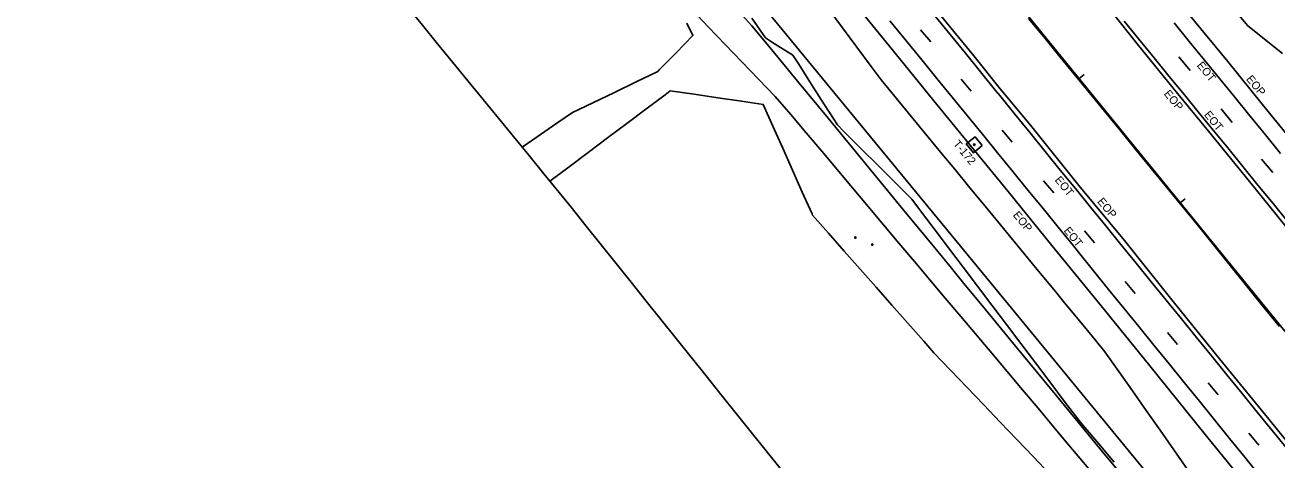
# Model space of a CAD drawing. Extents: x 2132221 to 2141942, y 535736 to 547298.
# Drawn here: x 2140649 to 2141431, y 536470 to 536742 of the extents above; entities that cross this region are included whole.
import ezdxf

# ---------------------------------------------------------------- set-up
doc = ezdxf.new("R2010")
doc.units = 0
for name, color, linetype in [('RD_EX_BldgApp', 7, 'Continuous'), ('RD_EX_Driveway', 7, 'Continuous'), ('RD_EX_Fence_Other', 7, 'Continuous'), ('RD_EX_GuardRail', 7, 'Continuous'), ('RD_EX_Misc', 7, 'Continuous'), ('RD_EX_Misc_txCode', 7, 'Continuous'), ('RD_EX_Road', 7, 'Continuous'), ('RD_EX_Road_txCode', 7, 'Continuous'), ('RD_EX_VEG', 7, 'Continuous'), ('RD_HC_Cl', 7, 'Continuous'), ('RD_HC_Data_Tic', 7, 'Continuous'), ('RD_HC_Survey', 7, 'Continuous'), ('RD_HC_Survey_txCode', 7, 'Continuous'), ('TOPO_E_TLIML-Line', 7, 'Continuous')]:
    doc.layers.add(name, color=color, linetype=linetype)

msp = doc.modelspace()

# ---------------------------------------------------------------- linework, layer by layer
at = {"layer": 'RD_EX_BldgApp'}
for centre in [(2141167.59, 536609.49), (2141178.05, 536605.08)]:
    msp.add_circle(centre, 0.444, dxfattribs=at)
at = {"layer": 'RD_EX_Driveway'}
for points in [[(2141320.28, 536456.77), (2141300.97, 536479.73), (2141291.31, 536491.21), (2141281.66, 536502.69), (2141272.01, 536514.17), (2141262.35, 536525.65), (2141252.7, 536537.13), (2141233.39, 536560.09), (2141223.74, 536571.58), (2141214.08, 536583.06), (2141204.43, 536594.54), (2141194.77, 536606.02), (2141185.12, 536617.5), (2141175.47, 536628.98), (2141165.81, 536640.46), (2141156.16, 536651.94), (2141146.5, 536663.42), (2141136.85, 536674.9), (2141127.19, 536686.38), (2141117.34, 536697.68), (2141106.96, 536708.51), (2141096.59, 536719.34), (2141086.21, 536730.17), (2141075.83, 536741), (2141065.45, 536751.83)], [(2141092.78, 536752.96), (2141102.88, 536741.95), (2141112.4, 536730.37), (2141121.92, 536718.79), (2141131.45, 536707.2), (2141150.49, 536684.03), (2141198.11, 536626.11), (2141217.15, 536602.94), (2141226.68, 536591.36), (2141236.2, 536579.77), (2141245.72, 536568.19), (2141255.24, 536556.6), (2141264.77, 536545.02), (2141293.34, 536510.26), (2141321.91, 536475.51), (2141331.43, 536463.93)]]:
    msp.add_lwpolyline(points, dxfattribs=at)
at = {"layer": 'RD_EX_Fence_Other'}
for points in [[(2140668.17, 537219.94), (2140829.5, 537021.77), (2140981.15, 536833.81), (2141060.72, 536813.9), (2141263.27, 536567.7)], [(2141580.4, 536180.84), (2141441.58, 536350.44), (2141263.27, 536567.7)]]:
    msp.add_lwpolyline(points, dxfattribs=at)
at = {"layer": 'RD_EX_GuardRail'}
msp.add_lwpolyline([(2141432.47, 536553.87), (2141423.05, 536565.55), (2141413.64, 536577.23), (2141404.22, 536588.91), (2141394.81, 536600.58), (2141385.39, 536612.26), (2141380.17, 536618.74), (2141370.68, 536630.35), (2141361.19, 536641.96), (2141351.69, 536653.58), (2141342.2, 536665.19), (2141332.71, 536676.81), (2141323.22, 536688.42), (2141313.73, 536700.04), (2141304.23, 536711.65), (2141294.74, 536723.27), (2141285.25, 536734.88), (2141275.76, 536746.5)], dxfattribs=at)
at = {"layer": 'RD_EX_Misc'}
for p, q in [((2141208.29, 536739.34), (2141214.58, 536731.82)), ((2141369.7, 536722.38), (2141376.72, 536713.93)), ((2141233.64, 536708.53), (2141239.94, 536701)), ((2141396, 536689.88), (2141403.02, 536681.43)), ((2141259.19, 536676.69), (2141265.49, 536669.16)), ((2141421.27, 536658.58), (2141428.29, 536650.13)), ((2141285.18, 536644.94), (2141291.47, 536637.42)), ((2141310.68, 536613.62), (2141316.98, 536606.09)), ((2141336.13, 536581.93), (2141342.43, 536574.4)), ((2141362.5, 536550.14), (2141368.8, 536542.62)), ((2141387.99, 536518.6), (2141394.29, 536511.08)), ((2141413.38, 536487.14), (2141419.68, 536479.62))]:
    msp.add_line(p, q, dxfattribs=at)
for points in [[(2141418.47, 536462.74), (2141410.79, 536472.18), (2141401.34, 536483.83), (2141391.9, 536495.48), (2141382.46, 536507.14), (2141373.01, 536518.79), (2141363.57, 536530.45), (2141354.12, 536542.1), (2141344.68, 536553.75), (2141335.24, 536565.41), (2141325.79, 536577.06), (2141316.35, 536588.72), (2141306.9, 536600.37), (2141303.74, 536604.27), (2141294.27, 536615.91), (2141284.8, 536627.54), (2141275.32, 536639.17), (2141265.85, 536650.8), (2141256.38, 536662.43), (2141246.91, 536674.06), (2141237.44, 536685.69), (2141227.97, 536697.32), (2141218.49, 536708.95), (2141209.02, 536720.59), (2141199.55, 536732.22), (2141198.62, 536733.36), (2141189.14, 536745)], [(2141217.34, 536747.97), (2141226.8, 536736.33), (2141236.26, 536724.69), (2141245.72, 536713.05), (2141255.18, 536701.41), (2141257.75, 536698.25), (2141267.21, 536686.61), (2141276.67, 536674.97), (2141286.13, 536663.33), (2141295.59, 536651.69), (2141305.05, 536640.05), (2141314.51, 536628.41), (2141323.97, 536616.77), (2141333.43, 536605.13), (2141342.89, 536593.49), (2141352.35, 536581.85), (2141361.81, 536570.21), (2141371.28, 536558.57), (2141380.74, 536546.93), (2141390.2, 536535.29), (2141399.66, 536523.65), (2141409.12, 536512.01), (2141418.58, 536500.37), (2141428.04, 536488.73), (2141437.5, 536477.09)], [(2141335.51, 536744.81), (2141344.69, 536733.47), (2141354.18, 536721.86), (2141363.67, 536710.24), (2141373.16, 536698.62), (2141382.65, 536687.01), (2141392.15, 536675.39), (2141400.17, 536665.57), (2141409.63, 536653.93), (2141419.1, 536642.3), (2141428.56, 536630.66), (2141438.03, 536619.02)], [(2141366.74, 536743.73), (2141376.2, 536732.1), (2141385.67, 536720.46), (2141395.13, 536708.82), (2141404.6, 536697.19), (2141414.06, 536685.55), (2141414.24, 536685.34), (2141423.71, 536673.71), (2141433.19, 536662.08)]]:
    msp.add_lwpolyline(points, dxfattribs=at)
at = {"layer": 'RD_EX_Road'}
for points in [[(2140918.19, 537312.33), (2140947.17, 537276.89), (2140973.09, 537245.24), (2141002.07, 537209.14), (2141026.69, 537178.71), (2141053.16, 537146.28), (2141085.78, 537106.42), (2141109.74, 537077.06), (2141135.97, 537044.44), (2141159.17, 537015.74), (2141186.81, 536981.82), (2141217.74, 536943.28), (2141243.15, 536912.57), (2141271.49, 536877.74), (2141303.6, 536838.39), (2141327.39, 536808.98), (2141353.08, 536777.18), (2141379.52, 536744.78), (2141400.21, 536719.53)], [(2140795.61, 537213.06), (2140823.89, 537178.06), (2140849.99, 537146.3), (2140880.39, 537109.04), (2140913.6, 537068.09), (2140939.63, 537035.66), (2140970.88, 536997.21), (2140996.08, 536966.07), (2141027.99, 536927.07), (2141056.39, 536892.33), (2141089.41, 536851.66), (2141105.84, 536831.36), (2141135.8, 536794.49), (2141165.59, 536757.61), (2141195.05, 536721.46), (2141216.63, 536694.89)], [(2140953.87, 537210.58), (2140961.83, 537201.04), (2140978.7, 537180.63), (2141002.17, 537151.39), (2141024.73, 537123.64), (2141051.32, 537091.01), (2141068.97, 537069.27), (2141094.06, 537038.43), (2141119.7, 537006.69), (2141143.72, 536977.47), (2141166.39, 536949.37), (2141199.9, 536908.09), (2141222.51, 536880.61), (2141248.63, 536848.33), (2141269.19, 536822.71), (2141284.6, 536803.08), (2141306.11, 536777.1), (2141327.49, 536750.79), (2141344.51, 536729.62), (2141368.02, 536700.55)], [(2140886.76, 537160.29), (2140895.38, 537149.14), (2140915.92, 537123.81), (2140935.24, 537100.19), (2140951.09, 537080.35), (2140968.56, 537058.94), (2140985.94, 537037.54), (2141007.77, 537010.42), (2141026.32, 536987.58), (2141049.36, 536959.41), (2141073.44, 536929.9), (2141102.76, 536893.77), (2141126.79, 536863.94), (2141154.32, 536830.11), (2141177.7, 536800.98), (2141202.73, 536770.53), (2141224.28, 536744.23), (2141241.5, 536723.01), (2141258.1, 536702.42), (2141276.91, 536679.79), (2141307.26, 536642.01)], [(2141400.21, 536719.53), (2141421.74, 536692.79), (2141446.41, 536662.42), (2141473.18, 536629.63), (2141493.96, 536603.95), (2141524.71, 536566.52), (2141554.5, 536530.06), (2141586.93, 536489.9), (2141617.57, 536452.29), (2141648.39, 536414.18), (2141680.48, 536374.6), (2141710.79, 536337.39), (2141745.16, 536295.03), (2141770.4, 536263.97), (2141771.11, 536263.1)], [(2141368.02, 536700.55), (2141388.12, 536676.09), (2141413.83, 536644.54), (2141435.69, 536617.51), (2141459.25, 536588.54), (2141482.94, 536559.36), (2141510.35, 536525.76), (2141540.71, 536488.31), (2141570.12, 536452.2), (2141596.11, 536420.21), (2141624.05, 536385.62), (2141647.18, 536357.24), (2141669.45, 536329.66), (2141696.49, 536296.47), (2141723.55, 536263.52), (2141742.18, 536240.44)], [(2141216.63, 536694.89), (2141233.5, 536674.27), (2141263.02, 536638.32), (2141290.32, 536604.48), (2141320.21, 536567.85), (2141351.55, 536529.15), (2141386.17, 536486.26), (2141419.26, 536445.76), (2141452.88, 536404.33), (2141483.81, 536366.13), (2141514.47, 536328.33), (2141545.32, 536290.68), (2141579.87, 536248.25), (2141615.32, 536204.38), (2141646.87, 536165.77)], [(2141307.26, 536642.01), (2141335.61, 536607.53), (2141366.18, 536569.41), (2141395.13, 536533.53), (2141423.12, 536499.29), (2141453.03, 536462.56), (2141489.25, 536418.1), (2141515.38, 536386.04), (2141548.03, 536345.82), (2141577.51, 536309.11), (2141608.77, 536270.83), (2141640.51, 536231.69), (2141674.06, 536190.78), (2141675.88, 536188.5)]]:
    msp.add_lwpolyline(points, dxfattribs=at)
at = {"layer": 'RD_EX_VEG'}
for points in [[(2141150.63, 536752.64), (2141159.55, 536740.58), (2141168.48, 536728.53), (2141177.4, 536716.47), (2141183.64, 536708.04), (2141193.17, 536696.46), (2141202.7, 536684.88), (2141212.23, 536673.29), (2141221.76, 536661.71), (2141229.58, 536652.19), (2141239.11, 536640.61), (2141248.64, 536629.03), (2141258.17, 536617.44), (2141263.91, 536610.46), (2141273.44, 536598.87), (2141282.97, 536587.29), (2141292.5, 536575.7), (2141298.25, 536568.72), (2141307.78, 536557.13), (2141317.3, 536545.55), (2141323.44, 536538.09), (2141332.06, 536525.81), (2141340.68, 536513.54), (2141349.3, 536501.26), (2141357.92, 536488.99), (2141366.54, 536476.71), (2141375.16, 536464.44)], [(2141403.31, 536753.09), (2141412.49, 536742.08), (2141424.21, 536732.71), (2141434.47, 536724.52)], [(2141062.2, 536743.48), (2141065.99, 536735.74), (2141055.5, 536725.02), (2141045.01, 536714.3), (2141044.02, 536713.29), (2141030.51, 536706.77), (2141017, 536700.25), (2141003.49, 536693.73), (2140990.74, 536687.57), (2140978.36, 536679.1), (2140965.98, 536670.63), (2140959.26, 536666.03)], [(2141329.25, 536469.09), (2141319.57, 536480.54), (2141309.89, 536492), (2141307.11, 536495.28), (2141298.08, 536507.25), (2141289.04, 536519.22), (2141280, 536531.2), (2141270.96, 536543.17), (2141261.92, 536555.14), (2141252.89, 536567.11), (2141243.85, 536579.08), (2141234.81, 536591.05), (2141225.77, 536603.02), (2141216.73, 536614.99), (2141207.69, 536626.97), (2141202.81, 536633.43), (2141192.2, 536644.04), (2141181.59, 536654.64), (2141170.98, 536665.24), (2141160.37, 536675.85), (2141156.32, 536679.89), (2141148.25, 536692.53), (2141140.17, 536705.18), (2141132.1, 536717.82), (2141128.43, 536723.56), (2141115.72, 536731.51), (2141111.34, 536734.25), (2141102.87, 536746.62)], [(2140976.69, 536644.72), (2140988.67, 536653.73), (2141000.66, 536662.75), (2141012.65, 536671.76), (2141024.64, 536680.78), (2141036.63, 536689.8), (2141048.61, 536698.81), (2141051.87, 536701.26), (2141066.71, 536699.08), (2141081.55, 536696.89), (2141096.39, 536694.71), (2141109.93, 536692.72), (2141116.03, 536679.02), (2141122.14, 536665.32), (2141128.25, 536651.62), (2141134.35, 536637.92), (2141140.46, 536624.22), (2141140.78, 536623.51), (2141150.69, 536612.26), (2141160.61, 536601.01), (2141170.53, 536589.75), (2141180.45, 536578.5), (2141190.37, 536567.25), (2141200.29, 536556), (2141210.21, 536544.75), (2141216.65, 536537.45), (2141227, 536526.6), (2141237.36, 536515.74), (2141247.71, 536504.89), (2141258.07, 536494.04), (2141268.42, 536483.19), (2141278.78, 536472.34), (2141289.13, 536461.48)]]:
    msp.add_lwpolyline(points, dxfattribs=at)
at = {"layer": 'RD_HC_Cl'}
msp.add_line((2136971.61, 542041.65), (2141699.63, 536226.46), dxfattribs=at)
at = {"layer": 'RD_HC_Data_Tic'}
for p, q in [((2141307.45, 536708.82), (2141310.56, 536711.34)), ((2141370.54, 536631.23), (2141373.64, 536633.75))]:
    msp.add_line(p, q, dxfattribs=at)
at = {"layer": 'RD_HC_Survey'}
msp.add_lwpolyline([(2141246.79, 536667.03), (2141242.29, 536672.49), (2141236.83, 536667.99), (2141241.33, 536662.53)], close=True, dxfattribs=at)
msp.add_circle((2141241.81, 536667.51), 0.5, dxfattribs=at)
at = {"layer": 'TOPO_E_TLIML-Line'}
msp.add_lwpolyline([(2140887.48, 536753.86), (2140896.97, 536742.24), (2140906.47, 536730.63), (2140915.96, 536719.01), (2140925.45, 536707.4), (2140934.95, 536695.79), (2140944.44, 536684.17), (2140953.93, 536672.56), (2140963.42, 536660.94), (2140972.92, 536649.33), (2140982.41, 536637.72), (2140990.04, 536628.38), (2140999.41, 536616.66), (2141008.77, 536604.94), (2141018.14, 536593.23), (2141027.5, 536581.51), (2141036.87, 536569.79), (2141046.23, 536558.08), (2141055.6, 536546.36), (2141064.96, 536534.64), (2141074.33, 536522.92), (2141083.69, 536511.21), (2141093.06, 536499.49), (2141102.42, 536487.77), (2141111.79, 536476.06), (2141121.15, 536464.34)], dxfattribs=at)

# ---------------------------------------------------------------- texts
at = {"layer": 'RD_EX_Misc_txCode'}
for p in [(2141380.58, 536717), (2141385.12, 536686.16), (2141291.84, 536645.35), (2141297.44, 536613.64)]:
    msp.add_text('EOT', height=5, rotation=309.5103, dxfattribs=at).set_placement(p)
at = {"layer": 'RD_EX_Road_txCode'}
for p in [(2141411.44, 536708.43), (2141360.01, 536699.25), (2141318.43, 536631.83), (2141265.69, 536623.4)]:
    msp.add_text('EOP', height=5, rotation=309.5103, dxfattribs=at).set_placement(p)
at = {"layer": 'RD_HC_Survey_txCode'}
msp.add_text('T-172', height=5, rotation=309.5103, dxfattribs=at).set_placement((2141228.32, 536667.88))

doc.saveas('drawing.dxf')
